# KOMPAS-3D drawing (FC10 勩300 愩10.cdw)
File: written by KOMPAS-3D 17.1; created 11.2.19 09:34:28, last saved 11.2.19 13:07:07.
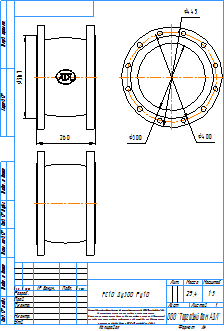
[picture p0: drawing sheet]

Sheet 1: A4, portrait

Title block, sheet 1: name: FC10 Ду300 Ру10; mass: 29,4; sheets: 1; sheet format: A4; stored path: \\adlc.lan\data\АДЛ_ПКД\3D-модели\ADL production\Гибкие вставки серии FC\FC10\KOMPAS 2D\FC10 Ду300 Ру10.cdw

Views: Вид 1
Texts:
  kka
  adl
  Рама для чертежей
  Лит-Масса-Масштаб
  Материал-Предприятие
  Масштаб
  Изм.
  Лист
  № докум.
  Подп.
  Дата
  Лит.
  Разраб.
  Пров.
  Т.контр.
  Листов
  Внимание! Данный продукт является объектом авторского права ООО «Торговый Дом АДЛ».
  Запрещается изменение, копирование, распространение
  (в том числе путем копирования на другие сайты и ресурсы в Интернете)
  или любое иное использование информации и объектов без предварительного
  согласия правообладателя (ООО «Торговый Дом АДЛ»).
  Н.контр.
  Утв.
  ООО "Торговый дом АДЛ"
  Изменение
  Номер документа
  Подпись
  Обозначение документа
  Наименование изделия
  Масса изделия по ГОСТ 2.109-73
  Порядковый номер листа
  Общее количество листов в документе
  Характер работы, выполненной лицом, подписавшим документ
  Наименование или индекс предприятия, выпускающего документ
  Инв. № подл.
  Подп. и дата
  Взам. инв. №
  Инв. № дубл.
  Инвентарный номер подлинника по ГОСТ 2.501-68
  Подпись принявшего подлинник в отдел технической документации
  Инвентарный номер подлинника, взамен которого выпущен данный подлинник
  Инвентарный номер дубликата по ГОСТ 2.502-68
  Подпись принявшего дубликат в отдел технической документации
  Справ. №
  Перв. примен.
  Обозначение документа, взамен или на основании которого выпущен данный документ
  Обозначение документа, в котором впервые записан данный документ
  Подпись лица, копировавшего чертеж
  Обозначение формата листа
  !Рама для чертежа
Dimensions and other numbers on the sheet: 260; 367; 300; 400; 445; 1:5; 1; 29,4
